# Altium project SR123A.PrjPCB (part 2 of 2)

## Sheet SR123A_OptExtLogic.SchDoc: LM51772RWE EVM OptExtLogic
size 431 x 279 mm; Date: Not shown in title block; ApprovedBy: Not shown in title block; CheckedBy: Not shown in title block; Author: Not shown in title block; CompanyName: Not shown in title block; Organization: Not shown in title block; Address1: Not shown in title block; Address2: Not shown in title block; Address3: Not shown in title block; Address4: Not shown in title block; DocumentNumber: 2; Revision: Use project parameter SCH_Rev; SheetNumber: 2; SheetTotal: 3; PageSetup: Record=PageOptions¦CenterHorizontal=True¦CenterVertical=True¦PrintScale=1.00¦XCorrection=1.00¦YCorrection=1.00¦PrintKind=0¦BorderSize=5000000¦LeftOffset=0¦BottomOffset=0¦Orientation=2¦PaperLength=1000¦PaperWidth=1000¦Scale=100¦PaperSource=15¦PrintQuality=600¦MediaType=1¦DitherType=10¦PaperKind=Letter¦PrintScaleMode=1
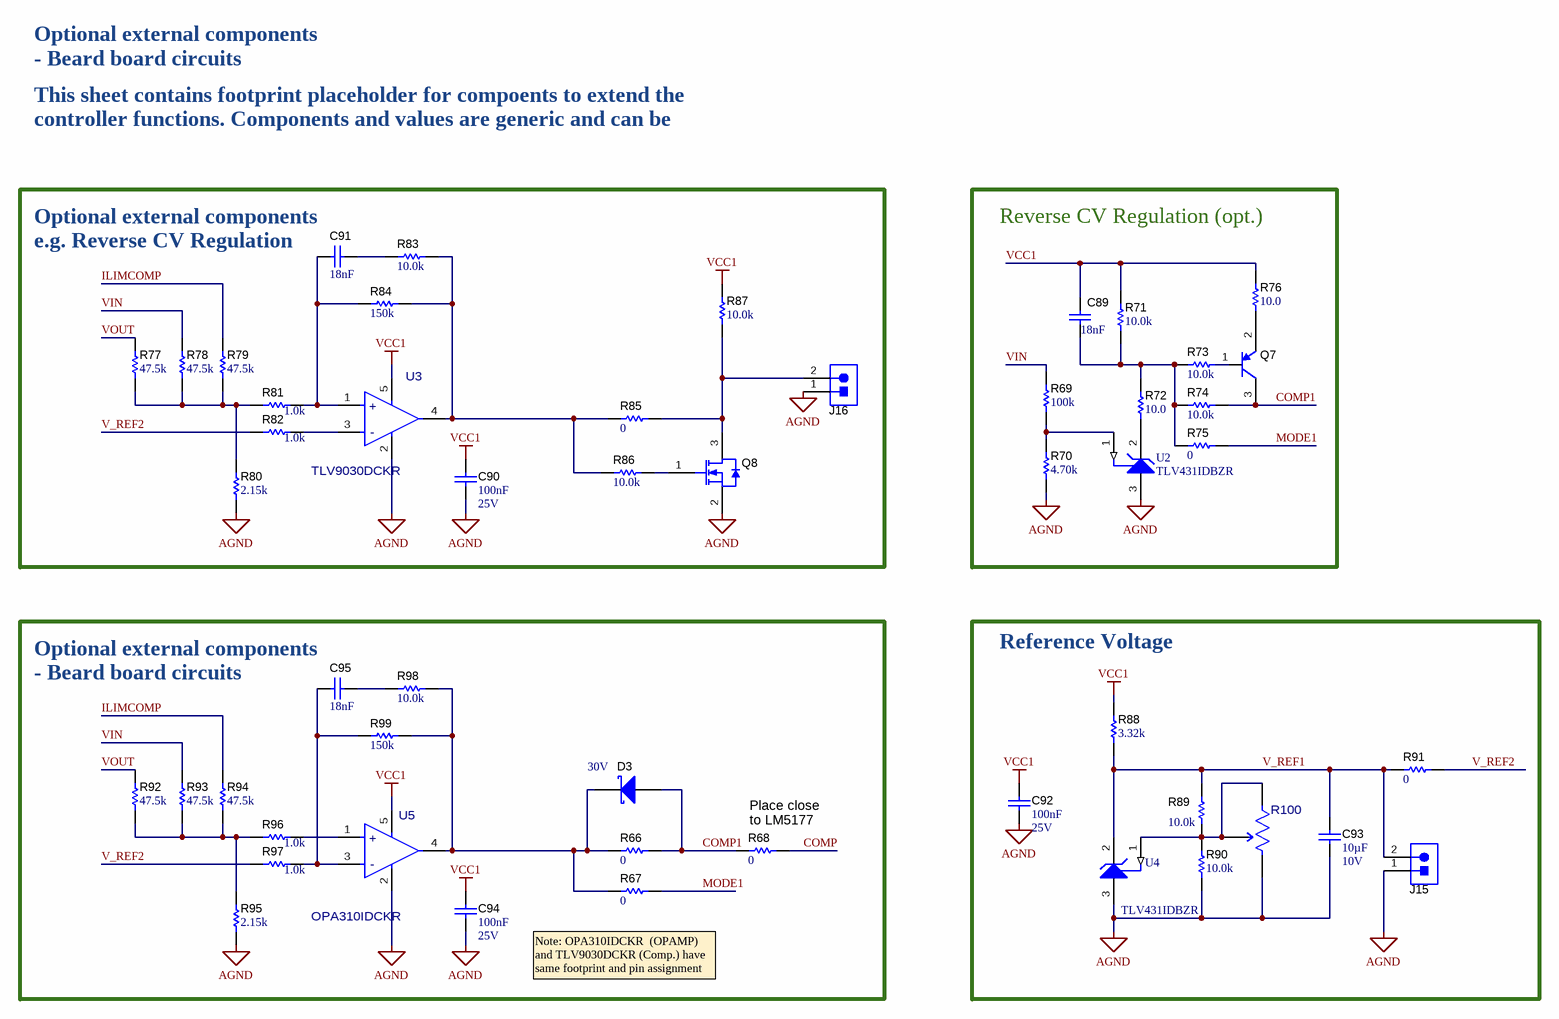
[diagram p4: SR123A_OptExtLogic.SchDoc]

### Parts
C89  Cap_F: 18nF  [0603S]  (hidden comment: C0603C183K1RACTU)
C90  Cap_F: 100nF  VDC_V: 25V  [0603S]  (hidden comment: C0603X104K3RACTU)
C91  Cap_F: 18nF  [0603S]  (hidden comment: C0603C183K1RACTU)
C92  Cap_F: 100nF  VDC_V: 25V  [0603S]  (hidden comment: C0603X104K3RACTU)
C93  ValueDisplayed: 10µF  VDC_V: 10V  [0603S]  (hidden comment: GRM188R61A106KE69D)
C94  Cap_F: 100nF  VDC_V: 25V  [0603S]  (hidden comment: C0603X104K3RACTU)
C95  Cap_F: 18nF  [0603S]  (hidden comment: C0603C183K1RACTU)
D3  value 30V  [SOD-123]  (hidden comment: BAT54T1G)
J15  61300211121  [WURTH_61300211121]  (value not drawn)
J16  61300211121  [WURTH_61300211121]  (value not drawn)
Q7  BC807-40LT1G  [SOT-23]  (value not drawn)
Q8  2N7002W-7-F  [SOT-323]  (value not drawn)
R66  ValueDisplayed: 0  [0603S]  (hidden comment: RMCF0603ZT0R00)
R67  ValueDisplayed: 0  [0603S]  (hidden comment: RMCF0603ZT0R00)
R68  ValueDisplayed: 0  [0603S]  (hidden comment: RMCF0603ZT0R00)
R69  ValueDisplayed: 100k  [0603S]  (hidden comment: RC0603FR-07100KL)
R70  ValueDisplayed: 4.70k  [0603S]  (hidden comment: RC0603FR-074K7L)
R71  ValueDisplayed: 10.0k  [0603S]  (hidden comment: CRCW060310K0FKEA)
R72  ValueDisplayed: 10.0  [0603S]  (hidden comment: RC0603FR-0710RL)
R73  ValueDisplayed: 10.0k  [0603S]  (hidden comment: CRCW060310K0FKEA)
R74  ValueDisplayed: 10.0k  [0603S]  (hidden comment: CRCW060310K0FKEA)
R75  ValueDisplayed: 0  [0603S]  (hidden comment: RMCF0603ZT0R00)
R76  ValueDisplayed: 10.0  [0603S]  (hidden comment: RC0603FR-0710RL)
R77  ValueDisplayed: 47.5k  [0603S]  (hidden comment: RC0603FR-0747K5L)
R78  ValueDisplayed: 47.5k  [0603S]  (hidden comment: RC0603FR-0747K5L)
R79  ValueDisplayed: 47.5k  [0603S]  (hidden comment: RC0603FR-0747K5L)
R80  ValueDisplayed: 2.15k  [0603S]  (hidden comment: RC0603FR-072K15L)
R81  ValueDisplayed: 1.0k  [0603S]  (hidden comment: RC0603JR-071KL)
R82  ValueDisplayed: 1.0k  [0603S]  (hidden comment: RC0603JR-071KL)
R83  ValueDisplayed: 10.0k  [0603S]  (hidden comment: CRCW060310K0FKEA)
R84  ValueDisplayed: 150k  [0603S]  (hidden comment: RC0603FR-07150KL)
R85  ValueDisplayed: 0  [0603S]  (hidden comment: RMCF0603ZT0R00)
R86  ValueDisplayed: 10.0k  [0603S]  (hidden comment: RT0603BRD0710KL)
R87  ValueDisplayed: 10.0k  [0603S]  (hidden comment: RT0603BRD0710KL)
R88  ValueDisplayed: 3.32k  [0603S]  (hidden comment: RC0603FR-073K32L)
R89  ValueDisplayed: 10.0k  [0603S]  (hidden comment: RT0603BRD0710KL)
R90  ValueDisplayed: 10.0k  [0603S]  (hidden comment: RT0603BRD0710KL)
R91  ValueDisplayed: 0  [0603S]  (hidden comment: RMCF0603ZT0R00)
R92  ValueDisplayed: 47.5k  [0603S]  (hidden comment: RC0603FR-0747K5L)
R93  ValueDisplayed: 47.5k  [0603S]  (hidden comment: RC0603FR-0747K5L)
R94  ValueDisplayed: 47.5k  [0603S]  (hidden comment: RC0603FR-0747K5L)
R95  ValueDisplayed: 2.15k  [0603S]  (hidden comment: RC0603FR-072K15L)
R96  ValueDisplayed: 1.0k  [0603S]  (hidden comment: RC0603JR-071KL)
R97  ValueDisplayed: 1.0k  [0603S]  (hidden comment: RC0603JR-071KL)
R98  ValueDisplayed: 10.0k  [0603S]  (hidden comment: CRCW060310K0FKEA)
R99  ValueDisplayed: 150k  [0603S]  (hidden comment: RC0603FR-07150KL)
R100  ST-5ETW103  [FP-ST-5ETW103_SMT3_6MM0_4MM3-MFG]  (value not drawn)
U2  TLV431IDBZR  [DBZ0003A_N]
U3  TLV9030DCKR  [DCK0005A-MFG]
U4  TLV431IDBZR  [DBZ0003A_N]
U5  OPA310IDCKR  [DCK0005A-MFG]

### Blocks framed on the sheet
Reverse CV Regulation (opt.): C89 Q7 R69-R76 U2

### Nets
AGND: C90.2 C92.2 C93.2 C94.2 J15.1 J16.1 Q8.2(S) R70.1 R80.1 R90.2 R95.1 R100.3 U2.3(ANODE) U3.2(V-) U4.3(ANODE) U5.2(V-)
VCC1: C89.1 C90.1 C92.1 C94.1 R71.2 R76.1 R87.1 R88.2 U3.5(V+) U5.5(V+)
COMP: R68.2
COMP1: D3.2(A) Q7.3(C) R66.1 R68.1 R74.1
ILIMCOMP: R79.2 R94.2
MODE1: R67.1 R75.1
V_REF1: C93.1 J15.2 R88.1 R89.1 R91.2 U4.2(CATHODE)
V_REF2: R82.1 R91.1 R97.1
VIN: R69.2 R78.2 R93.2
VOUT: R77.2 R92.2
NetC89_2: C89.2 R71.1 R72.2 R73.2 R74.2 R75.2
NetC91_1: C91.1 R81.2 R84.1 U3.1(IN+)
NetC91_2: C91.2 R83.2
NetC95_1: C95.1 R97.2 R99.1 U5.3(IN-)
NetC95_2: C95.2 R98.2
NetD3_1: D3.1(K) R66.2 R67.2 R98.1 R99.2 U5.4(OUT)
NetJ16_2: J16.2 Q8.3(D) R85.1 R87.2
NetQ7_1: Q7.1(B) R73.1
NetQ7_2: Q7.2(E) R76.2
NetQ8_1: Q8.1(G) R86.2
NetR69_1: R69.1 R70.2 U2.1(REF)
NetR72_1: R72.1 U2.2(CATHODE)
NetR77_1: R77.1 R78.1 R79.1 R80.2 R81.1
NetR82_2: R82.2 U3.3(IN-)
NetR83_1: R83.1 R84.2 R85.2 R86.1 U3.4(OUT)
NetR89_2: R89.2 R90.1 R100.1 R100.2 U4.1(REF)
NetR92_1: R92.1 R93.1 R94.1 R95.2 R96.1
NetR96_2: R96.2 U5.1(IN+)

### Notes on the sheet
- Optional external components - Beard board circuits
- This sheet contains footprint placeholder for compoents to extend the controller functions. Components and values are generic and can be adjusted as required.
- (near C91) Optional external components e.g. Reverse CV Regulation
- (near C95) Optional external components - Beard board circuits
- (near R88) Reference Voltage
- (near R68) Place close
  to LM5177
- (near R67) Note: OPA310IDCKR  (OPAMP) and TLV9030DCKR (Comp.) have same footprint and pin assignment

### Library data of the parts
C89 C91 C95 = CMP-0006889-4: CAP, CERM, 0.018 uF, 100 V, +/- 10%, X7R, 0603; Manufacturer: Kemet; TaMin_C: -55°C; Polarized: N; SizeAreaWB_mm2: 4.68; Value1: Unknown; U/M: EA; TaMax_C: 125°C; SizeZ_mm: 1; SizeX_mm: 1.6; SizeY_mm: 0.8; Cap_Case: 0603; Value2: 100V; SizeArea_mm2: 1.28; AEC Category: Q200
C90 C92 C94 = CMP-0006979-5: CAP, CERM, 0.1 uF, 25 V, +/- 10%, X7R, 0603; Manufacturer: Kemet; TaMin_C: -55°C; Polarized: N; SizeAreaWB_mm2: 4.68; Value1: Unknown; U/M: EA; Value: 0.1uF; TaMax_C: 125°C; SizeZ_mm: 1; SizeX_mm: 1.6; SizeY_mm: 0.8; Cap_Case: 0603; SizeArea_mm2: 1.28; AEC Category: Q200
C93 = CMP-0085855-1: CAP, CERM, 10 µF, 10 V,+/- 10%, X5R, 0603; Manufacturer: MuRata; SizeX_mm: 1.6; SizeAreaWB_mm2: 4.68; Green_REACh: Incomplete; AEC Category: Q200; SizeArea_mm2: 1.28; SizeY_mm: 0.8; Green_Lifecycle: Active; TaMax_C: 85°C; Cap_Case: 0603; Value: 10uF; U/M: EA; Polarized: N; TaMin_C: -55°C; SizeZ_mm: 1
D3 = CMP-0028457-2: Diode, Schottky, 30 V, 0.2 A, SOD-123; Manufacturer: ON Semiconductor; SizeArea_mm2: 6.545; Io_A: 200mA; SizeX_mm: 3.85; Value1: 0.2A; SizeY_mm: 1.7; AEC Category: Q101; Vf_V: 800mV; TJmax_C: 125°C; Green_Lifecycle: Not Set; RJC_CperW: 174; Value2: 0.8V; SizeAreaWB_mm2: 13.095; Green_REACh: Incomplete; SizeZ_mm: 1.35
J15 J16 = CMP-0054794-2: Header, 2.54 mm, 2x1, Gold, TH; Manufacturer: Wurth Elektronik; Shrouded: N; Gender: Male; Green_REACh: Passed; Pitch_mm: 2.54; Green_Lifecycle: Active; Row_Count: 1; Cert_UL: Y
Q7 = CMP-0000367-2: Transistor, PNP, 45 V, 0.5 A, AEC-Q101, SOT-23; Manufacturer: ON Semiconductor; TaMax_C: 150°C; Value2: 600; Value1: 0.5 A; Vcesat1_V: 700mV; SizeX_mm: 2.5; SizeY_mm: 3; TaMin_C: -55°C; IcRated_A: 500mA; CompType: BJT; SizeZ_mm: 1.1; AEC Qualified: Y; Value: 45 V; SizeArea_mm2: 7.5; NPN: 0; Vceo_V: 45V; PNP: 1; AEC Category: Q101; SizeAreaWB_mm2: 14; U/M: EA
Q8 = CMP-0000776-1: MOSFET, N-CH, 60 V, 0.115 A, SOT-323; Alternate Manufacturer: None; Manufacturer: Diodes Inc.; SizeZ_mm: 1.1; ChType: N; Value1: 7; VdsMax_V: 60V; SizeX_mm: 2.2; Vgs_V: 20V; Value: 60V; Rdson45_ohm: 7.5; SizeArea_mm2: 4.84; AEC Category: Q101; IdsMax_A: 1.15dA; SizeAreaWB_mm2: 10.24; U/M: EA
R66-R68 R75 R85 R91 = CMP-0023343-3: RES, 0, 1%, 0.1 W, AEC-Q200 Grade 0, 0603; Manufacturer: Stackpole Electronics Inc; Power_W: 100mW; TempCo: ppm/C; U/M: EA; Value: 0; SizeX_mm: 1.6; SizeY_mm: 0.8; SizeZ_mm: 1; Value2: 0.1W; SizeArea_mm2: 1.28; AEC Qualified: Y; AEC Category: Q200
R69 = CMP-0022735-5: RES, 100 k, 1%, 0.1 W, 0603; Manufacturer: Yageo; Power_W: 100mW; TempCo: 100 ppm/C; Value: 100k; EIA_Code: E96; SizeX_mm: 1.6; SizeY_mm: 0.8; SizeZ_mm: 1; Value2: 0.1W; SizeArea_mm2: 1.28; AEC Qualified: N; VDC_V: 75V; AEC Category: Q200; SizeAreaWB_mm2: 4.68
R70 = CMP-0023153-5: RES, 4.70 k, 1%, 0.1 W, 0603; Manufacturer: Yageo; Power_W: 100mW; TempCo: 100 ppm/C; Value_Code: 4k70; Value: 4.70k; Res_ohm: 4.7k; SizeX_mm: 1.6; SizeY_mm: 0.8; SizeZ_mm: 1; Value2: 0.1W; SizeArea_mm2: 1.28; AEC Qualified: N; VDC_V: 75V; AEC Category: Q200; SizeAreaWB_mm2: 4.68
R71 R73 R74 R83 R98 = CMP-0021998-4: RES, 10.0 k, 1%, 0.1 W, AEC-Q200 Grade 0, 0603; Manufacturer: Vishay-Dale; Power_W: 100mW; TempCo: 100 ppm/C; Value_Code: 10k0; Value: 10.0k; EIA_Code: E96; Res_ohm: 10k; SizeX_mm: 1.6; SizeY_mm: 0.8; SizeZ_mm: 1; Value2: 0.1W; SizeArea_mm2: 1.28; AEC Qualified: Y; VDC_V: 75V; AEC Category: Q200; AEC Grade: 0
R72 R76 = CMP-0022751-4: RES, 10.0, 1%, 0.1 W, 0603; Manufacturer: Yageo; Power_W: 100mW; TempCo: 100 ppm/C; Value_Code: 10R0; Value: 10.0; EIA_Code: E96; Res_ohm: 10; SizeX_mm: 1.6; SizeY_mm: 0.8; SizeZ_mm: 1; Value2: 0.1W; SizeArea_mm2: 1.28; AEC Qualified: N; VDC_V: 75V; AEC Category: Q200; SizeAreaWB_mm2: 4.68
R77-R79 R92-R94 = CMP-0023132-5: RES, 47.5 k, 1%, 0.1 W, 0603; Manufacturer: Yageo; Power_W: 100mW; TempCo: 100 ppm/C; Value_Code: 47k5; Value: 47.5k; EIA_Code: E96; SizeX_mm: 1.6; SizeY_mm: 0.8; SizeZ_mm: 1; Value2: 0.1W; SizeArea_mm2: 1.28; AEC Qualified: N; VDC_V: 75V; AEC Category: Q200; SizeAreaWB_mm2: 4.68
R80 R95 = CMP-0022982-5: RES, 2.15 k, 1%, 0.1 W, 0603; Manufacturer: Yageo; Power_W: 100mW; TempCo: 100 ppm/C; Value_Code: 2k15; Value: 2.15k; EIA_Code: E96; SizeX_mm: 1.6; SizeY_mm: 0.8; SizeZ_mm: 1; Value2: 0.1W; SizeArea_mm2: 1.28; AEC Qualified: N; VDC_V: 75V; AEC Category: Q200; SizeAreaWB_mm2: 4.68
R81 R82 R96 R97 = CMP-0025899-5: RES, 1.0 k, 5%, 0.1 W, 0603; Manufacturer: Yageo; Power_W: 100mW; TempCo: 100 ppm/C; Value_Code: 1k00; Value: 1.0k; EIA_Code: E24; Res_ohm: 1k; SizeX_mm: 1.6; SizeY_mm: 0.8; SizeZ_mm: 1; Value2: 0.1W; SizeArea_mm2: 1.28; AEC Qualified: N; VDC_V: 75V; AEC Category: Q200; SizeAreaWB_mm2: 4.68
R84 R99 = CMP-0022808-4: RES, 150 k, 1%, 0.1 W, 0603; Manufacturer: Yageo; Power_W: 100mW; TempCo: 100 ppm/C; Value: 150k; EIA_Code: E96; SizeX_mm: 1.6; SizeY_mm: 0.8; SizeZ_mm: 1; Value2: 0.1W; SizeArea_mm2: 1.28; AEC Qualified: N; VDC_V: 75V; AEC Category: Q200; SizeAreaWB_mm2: 4.68
R86 R87 R89 R90 = CMP-0023653-3: RES, 10.0 k, 0.1%, 0.1 W, 0603; Manufacturer: Yageo America; Power_W: 100mW; TempCo: 25 ppm/C; Value_Code: 10k0; U/M: EA; Value: 10.0k; EIA_Code: E192; Res_ohm: 10k; SizeX_mm: 1.6; SizeY_mm: 0.8; SizeZ_mm: 1; Value2: 0.1W; SizeArea_mm2: 1.28; VDC_V: 75V; AEC Category: Q200
R88 = CMP-0023080-5: RES, 3.32 k, 1%, 0.1 W, 0603; Manufacturer: Yageo; Power_W: 100mW; TempCo: 100 ppm/C; Value_Code: 3k32; Value: 3.32k; EIA_Code: E96; SizeX_mm: 1.6; SizeY_mm: 0.8; SizeZ_mm: 1; Value2: 0.1W; SizeArea_mm2: 1.28; AEC Qualified: N; VDC_V: 75V; AEC Category: Q200; SizeAreaWB_mm2: 4.68
R100 = CMP-0092665-1: 10 kOhms 0.25W, 1/4W Gull Wing Surface Mount Trimmer Potentiometer Cermet 14.0 Turn Top Adjustment; Manufacturer: Nidec Copal Electronics; TempCo: 100ppm/°C; AEC Qualified: No; SizeZ_mm: 8.35mm; Res_ohm: 10kΩ; Value: 10kΩ; VDC_V: 50V; Tolerance_%: 10%
U2 U4 = CMP-0032976-1: Low Voltage Adjustable Precision Shunt Regulator, 39 ppm / degC, 15 mA, -40 to 85 degC, 3-pin SOT-23 (DBZ), Green (RoHS & no Sb/Br); Manufacturer: Texas Instruments; Rating: Catalog; Iout/Iz(Max)(mA): 15; SubFamily: Shunt Voltage Reference; VO Adj(Min)(V): 1.24; Temp Coeff(Max)(ppm/ degree C): 129; Temp Coeff(Typ)(ppm/ degree C): 39; VO Adj(Max)(V): 6; Initial Accuracy @ 25/deg C(%): 1.5; Min Iz for Regulation(uA): 80
U3 = CMP-0122166-1: Single low-voltage comparator with push-pull output 5-SC70 -40 to 125; Manufacturer: Texas Instruments; SizeZ_mm: 1.1mm; AEC Qualified: No; Input Bias Current: 0.000005uA; Input Offset Voltage: 0.3mV; Max Supply Voltage: 5.5V; Min Supply Voltage: 1.65V; Nominal Supply Current: 17.1uA; Number Of Channels: 1; Output Current Per Channel: 100mA; Standoff Height: 0mm; TaMax_C: +125°C; TaMin_C: -40°C; TJmax_C: +150°C; Voltage Gain: 200V/mV
U5 = CMP-0033571-1: Single, 5.5-V, 3-MHz high-output-current (150 mA) fast-shutdown (1 μs) operational amplifier 5-SC70 -40 to 125; Manufacturer: Texas Instruments; SizeZ_mm: 1.1mm; AEC Qualified: No; Gain Bandwidth: 3MHz; Input Bias Current: 0.000001uA; Input Offset Voltage: 0.25mV; Max Dual Supply Voltage: 2.75V; Max Supply Voltage: 5.5V; Min Dual Supply Voltage: 750mV; Min Supply Voltage: 1.5V; Nominal Supply Current: 165uA; Number Of Channels: 1; Output Current Per Channel: 20mA; Response Time: 2.3us; Standoff Height: 0mm; TaMax_C: +125°C; TaMin_C: -40°C; TJmax_C: +150°C; Voltage Gain: 125dB

## Sheet SR123A_Hardware.SchDoc: LM51772RWE EVM Hardware
size 431 x 279 mm; Date: Not shown in title block; ApprovedBy: Not shown in title block; CheckedBy: Not shown in title block; Author: Not shown in title block; CompanyName: Not shown in title block; Engineer: Not shown in title block; Organization: Not shown in title block; Address1: Not shown in title block; Address2: Not shown in title block; Address3: Not shown in title block; Address4: Not shown in title block; DocumentNumber: 3; Revision: Use project parameter SCH_Rev; SheetNumber: 3; SheetTotal: 3; PageSetup: Record=PageOptions¦CenterHorizontal=True¦CenterVertical=True¦PrintScale=1.00¦XCorrection=1.00¦YCorrection=1.00¦PrintKind=0¦BorderSize=5000000¦LeftOffset=0¦BottomOffset=0¦Orientation=2¦PaperLength=1000¦PaperWidth=1000¦Scale=100¦PaperSource=15¦PrintQuality=600¦MediaType=1¦DitherType=10¦PaperKind=Letter¦PrintScaleMode=1
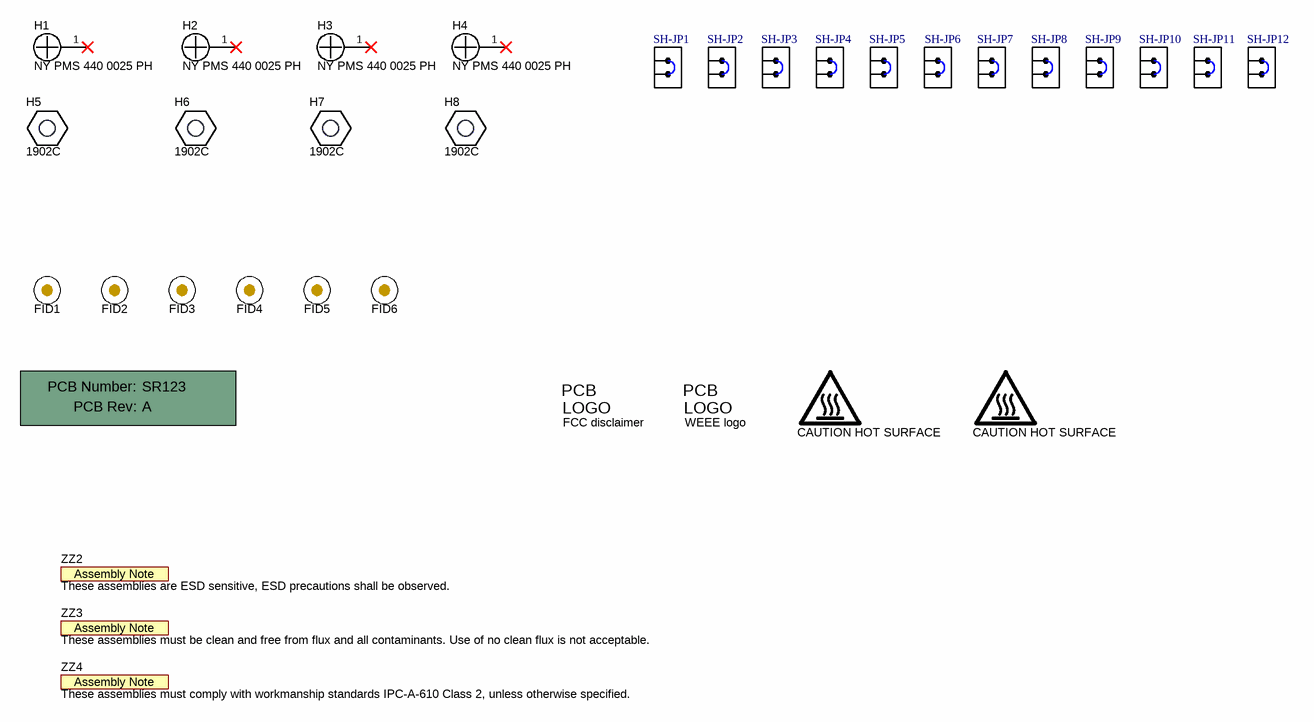
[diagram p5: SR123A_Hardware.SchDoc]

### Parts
!PCB  Printed Circuit Board  (value not drawn)  (mechanical)
FID1  Fiducial  [Fiducial10-20]  (value not drawn)
FID2  Fiducial  [Fiducial10-20]  (value not drawn)
FID3  Fiducial  [Fiducial10-20]  (value not drawn)
FID4  Fiducial  [Fiducial10-20]  (value not drawn)
FID5  Fiducial  [Fiducial10-20]  (value not drawn)
FID6  Fiducial  [Fiducial10-20]  (value not drawn)
H1  NY PMS 440 0025 PH  [NY PMS 440 0025 PH]
H2  NY PMS 440 0025 PH  [NY PMS 440 0025 PH]
H3  NY PMS 440 0025 PH  [NY PMS 440 0025 PH]
H4  NY PMS 440 0025 PH  [NY PMS 440 0025 PH]
H5  1902C  [Keystone_1902C]
H6  1902C  [Keystone_1902C]
H7  1902C  [Keystone_1902C]
H8  1902C  [Keystone_1902C]
Logo3  FCC disclaimer  [FCC_disclaimer]  (no BOM)
Logo4  WEEE logo  [WEEE_Minimum]  (no BOM)
Logo5  CAUTION HOT SURFACE  [IEC_HotSurface_Small]  (no BOM)
Logo6  CAUTION HOT SURFACE  [IEC_HotSurface_Small]  (no BOM)
SH-JP1  M7582-05  [Harwin_M7582-05]  (value not drawn)
SH-JP2  M7582-05  [Harwin_M7582-05]  (value not drawn)
SH-JP3  M7582-05  [Harwin_M7582-05]  (value not drawn)
SH-JP4  M7582-05  [Harwin_M7582-05]  (value not drawn)
SH-JP5  M7582-05  [Harwin_M7582-05]  (value not drawn)
SH-JP6  M7582-05  [Harwin_M7582-05]  (value not drawn)
SH-JP7  M7582-05  [Harwin_M7582-05]  (value not drawn)
SH-JP8  M7582-05  [Harwin_M7582-05]  (value not drawn)
SH-JP9  M7582-05  [Harwin_M7582-05]  (value not drawn)
SH-JP10  M7582-05  [Harwin_M7582-05]  (value not drawn)
SH-JP11  M7582-05  [Harwin_M7582-05]  (value not drawn)
SH-JP12  M7582-05  [Harwin_M7582-05]  (value not drawn)
ZZ2  These assemblies are ESD sensitive, ESD precautions shall be observed.  [AssemblyNote]  (no BOM)
ZZ3  These assemblies must be clean and free from flux and all contaminants. Use of no clean flux is not acceptable.  [AssemblyNote]  (no BOM)
ZZ4  These assemblies must comply with workmanship standards IPC-A-610 Class 2, unless otherwise specified.  [AssemblyNote]  (no BOM)

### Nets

Not connected (* = marked no-connect by the designer): H1 1*; H2 1*; H3 1*; H4 1*

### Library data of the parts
!PCB = CMP-0003618-2: Manufacturer: Any; PartNumber: SR123
FID1-FID6 = CMP-0077181-1: Fiducial mark.  There is nothing to buy or mount.
H1-H4 = CMP-0003617-1: Machine Screw, Round, #4-40 x 1/4, Nylon, Philips panhead; Manufacturer: B&F Fastener Supply; CompType: Hardware
H5-H8 = CMP-0003610-1: Standoff, Hex, 0.5"L #4-40 Nylon; Manufacturer: Keystone; CompType: Hardware
Logo3 = CMP-0074847-1: FCC_disclaimer; Library Reference: Logo
Logo4 = CMP-0074769-4: Manufacturer: Texas Instruments; CompType: IC; AEC Category: Q200
Logo5 Logo6 = CMP-0074837-2: IEC 61010-1 Hot Surface Warning; Manufacturer: Texas Instruments; SymbolCreator: a0412235; CompType: IC; AEC Category: Q200
SH-JP1-SH-JP12 = CMP-0078738-1: Single Operation 2.54mm Pitch Open Top Jumper Socket; Manufacturer: Harwin
ZZ2 = CMP-0077236-1
ZZ3 = CMP-0077237-1
ZZ4 = CMP-0077238-1

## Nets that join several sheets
AGND: SR123A (62 pins), SR123A_OptExtLogic (16 pins)
VCC1: SR123A (C37.2 J13.1 U1.1), SR123A_OptExtLogic (10 pins)
COMP: SR123A (C43.1 R32.2 TP13.1 U1.13), SR123A_OptExtLogic (R68.2)
ILIMCOMP: SR123A (5 pins), SR123A_OptExtLogic (R79.2 R94.2)
MODE1: SR123A (JP1.2 R22.1), SR123A_OptExtLogic (R67.1 R75.1)
VIN: SR123A (31 pins), SR123A_OptExtLogic (R69.2 R78.2 R93.2)
VOUT: SR123A (44 pins), SR123A_OptExtLogic (R77.2 R92.2)

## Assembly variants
001: not fitted C46 C49 C50 C51 C52 C53 C54 C55 C56 C57 C58 C59 C60 C61 C62 C63 C64 C65 C66 C67 C68 C69 C70 C71 C72 C73 C74 C75 C76 C77 C78 C79 C80 C81 C82 C83 C84 C85 C86 C87 C88 C89 C90 C91 C92 C93 C94 C95 D2 D3 FID1 FID2 FID3 H1 H2 H3 H4 H5 H6 H7 H8 J15 J16 Q1A Q2A Q3A Q4A Q6 Q7 Q8 R36 R55 R56 R57 R58 R59 R60 R61 R62 R63 R64 R65 R69 R70 R71 R72 R73 R74 R75 R76 R77 R78 R79 R80 R81 R82 R83 R84 R85 R86 R87 R88 R89 R90 R91 R92 R93 R94 R95 R96 R97 R98 R99 R100 R101 R102 R103 SH-JP5 SH-JP6 SH-JP8 TP9 TP12 TP13 TP14 TP15 U2 U3 U4 U5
